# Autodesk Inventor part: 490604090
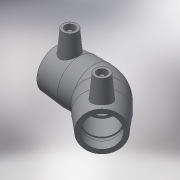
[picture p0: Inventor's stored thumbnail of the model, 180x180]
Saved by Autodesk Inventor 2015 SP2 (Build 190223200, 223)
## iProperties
Created: 2017-06
Part Number: 490604090
Material: Generic
Description: PLASSON 45° ELBOW 90
Document SubType Name: Modeling
Designer: KIM
Mass: 55.0731 g
Surface Area: 148.067 cm^2
Volume: 55.0731 cm^3
Density: 1 g/cm^3
Appearance: Default
Author: KIM
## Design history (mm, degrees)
derived "490604.ipt"
feature "Solid1::490604.ipt"
tag "TaggingFeature1"
body "Solid1"
other parameters: "d2" = 112, "d4" = 60.75, "d5" = 100.8, "d8" = 168 deg, "d11" = 10, "d14" = 17.6296, "d19" = 3.52592, "d20" = 168 deg, "d22" = 103.04, "d23" = 112, "d24" = 99.9488, "d29" = 69, "d30" = 15, "d31" = 85.05, "d34" = 5 deg, "d35" = 15, "d39" = 5 deg, "d41" = 4, "d42" = 14, "d43" = 0, "d45" = 4, "d46" = 14, "d47" = 0, "d50" = 76.5, "d52" = 75, "d54" = 135 deg, "d67" = 45 deg, "d71" = 135 deg, "d75" = 5.6, "d82" = 45 deg, "d83" = 75, "d84" = 100.8, "d86" = 50.4, "d87" = 135 deg, "d88" = 243, "d90" = 75, "d91" = 0, "d92" = 75, "d93" = 0, "d94" = 135 deg, "d95" = 51.52, "d98" = 243, "d99" = 72.9, "d101" = 3, "d102" = 0, "d103" = 3, "d104" = 0, "d105" = 21.75, "d106" = 5.4375, "L_" = 243, "L_1" = 75, "D_" = 112, "A_" = 69, "d_2" = 12
